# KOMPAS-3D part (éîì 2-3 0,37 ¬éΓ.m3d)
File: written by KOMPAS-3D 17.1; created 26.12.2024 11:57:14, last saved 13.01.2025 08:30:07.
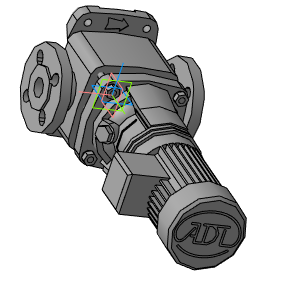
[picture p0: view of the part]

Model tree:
1. Операция без истории:3  (labels: ВМН 2-3 0,37 кВт)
